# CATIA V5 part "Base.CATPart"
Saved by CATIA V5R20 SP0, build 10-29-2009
Part number: Barre1
Publications: "Base", "Pivot0/3", "Pivot0/1"
Bounding box of the stored display mesh (mm): x 0 to 9.948, y 0 to 38.743, z -5 to 5
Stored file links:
  C:\Users\Admin\Desktop\IAO\Base.CATPart
  C:\Users\Admin\Desktop\IAO\Skl_4barres.CATProduct
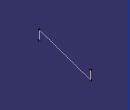
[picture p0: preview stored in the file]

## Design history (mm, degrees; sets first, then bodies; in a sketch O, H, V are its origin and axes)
Set1
  Point1 "Point A": linked copy from another document
  Point2 "Point B": linked copy from another document
  Plane1 "Plan ref": linked copy from another document
Set2
  Line1 "Base": type PtPt, FirstPoint Point1, SecondPoint Point2
  Line2 "Pivot0/3": type PtDir, RefPoint Point2, Direction Plane1, Start 0, End 5
  Line3 "Pivot0/1": type PtDir, RefPoint Point1, Direction Plane1, Start 0, End 5
Body1 (main body)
